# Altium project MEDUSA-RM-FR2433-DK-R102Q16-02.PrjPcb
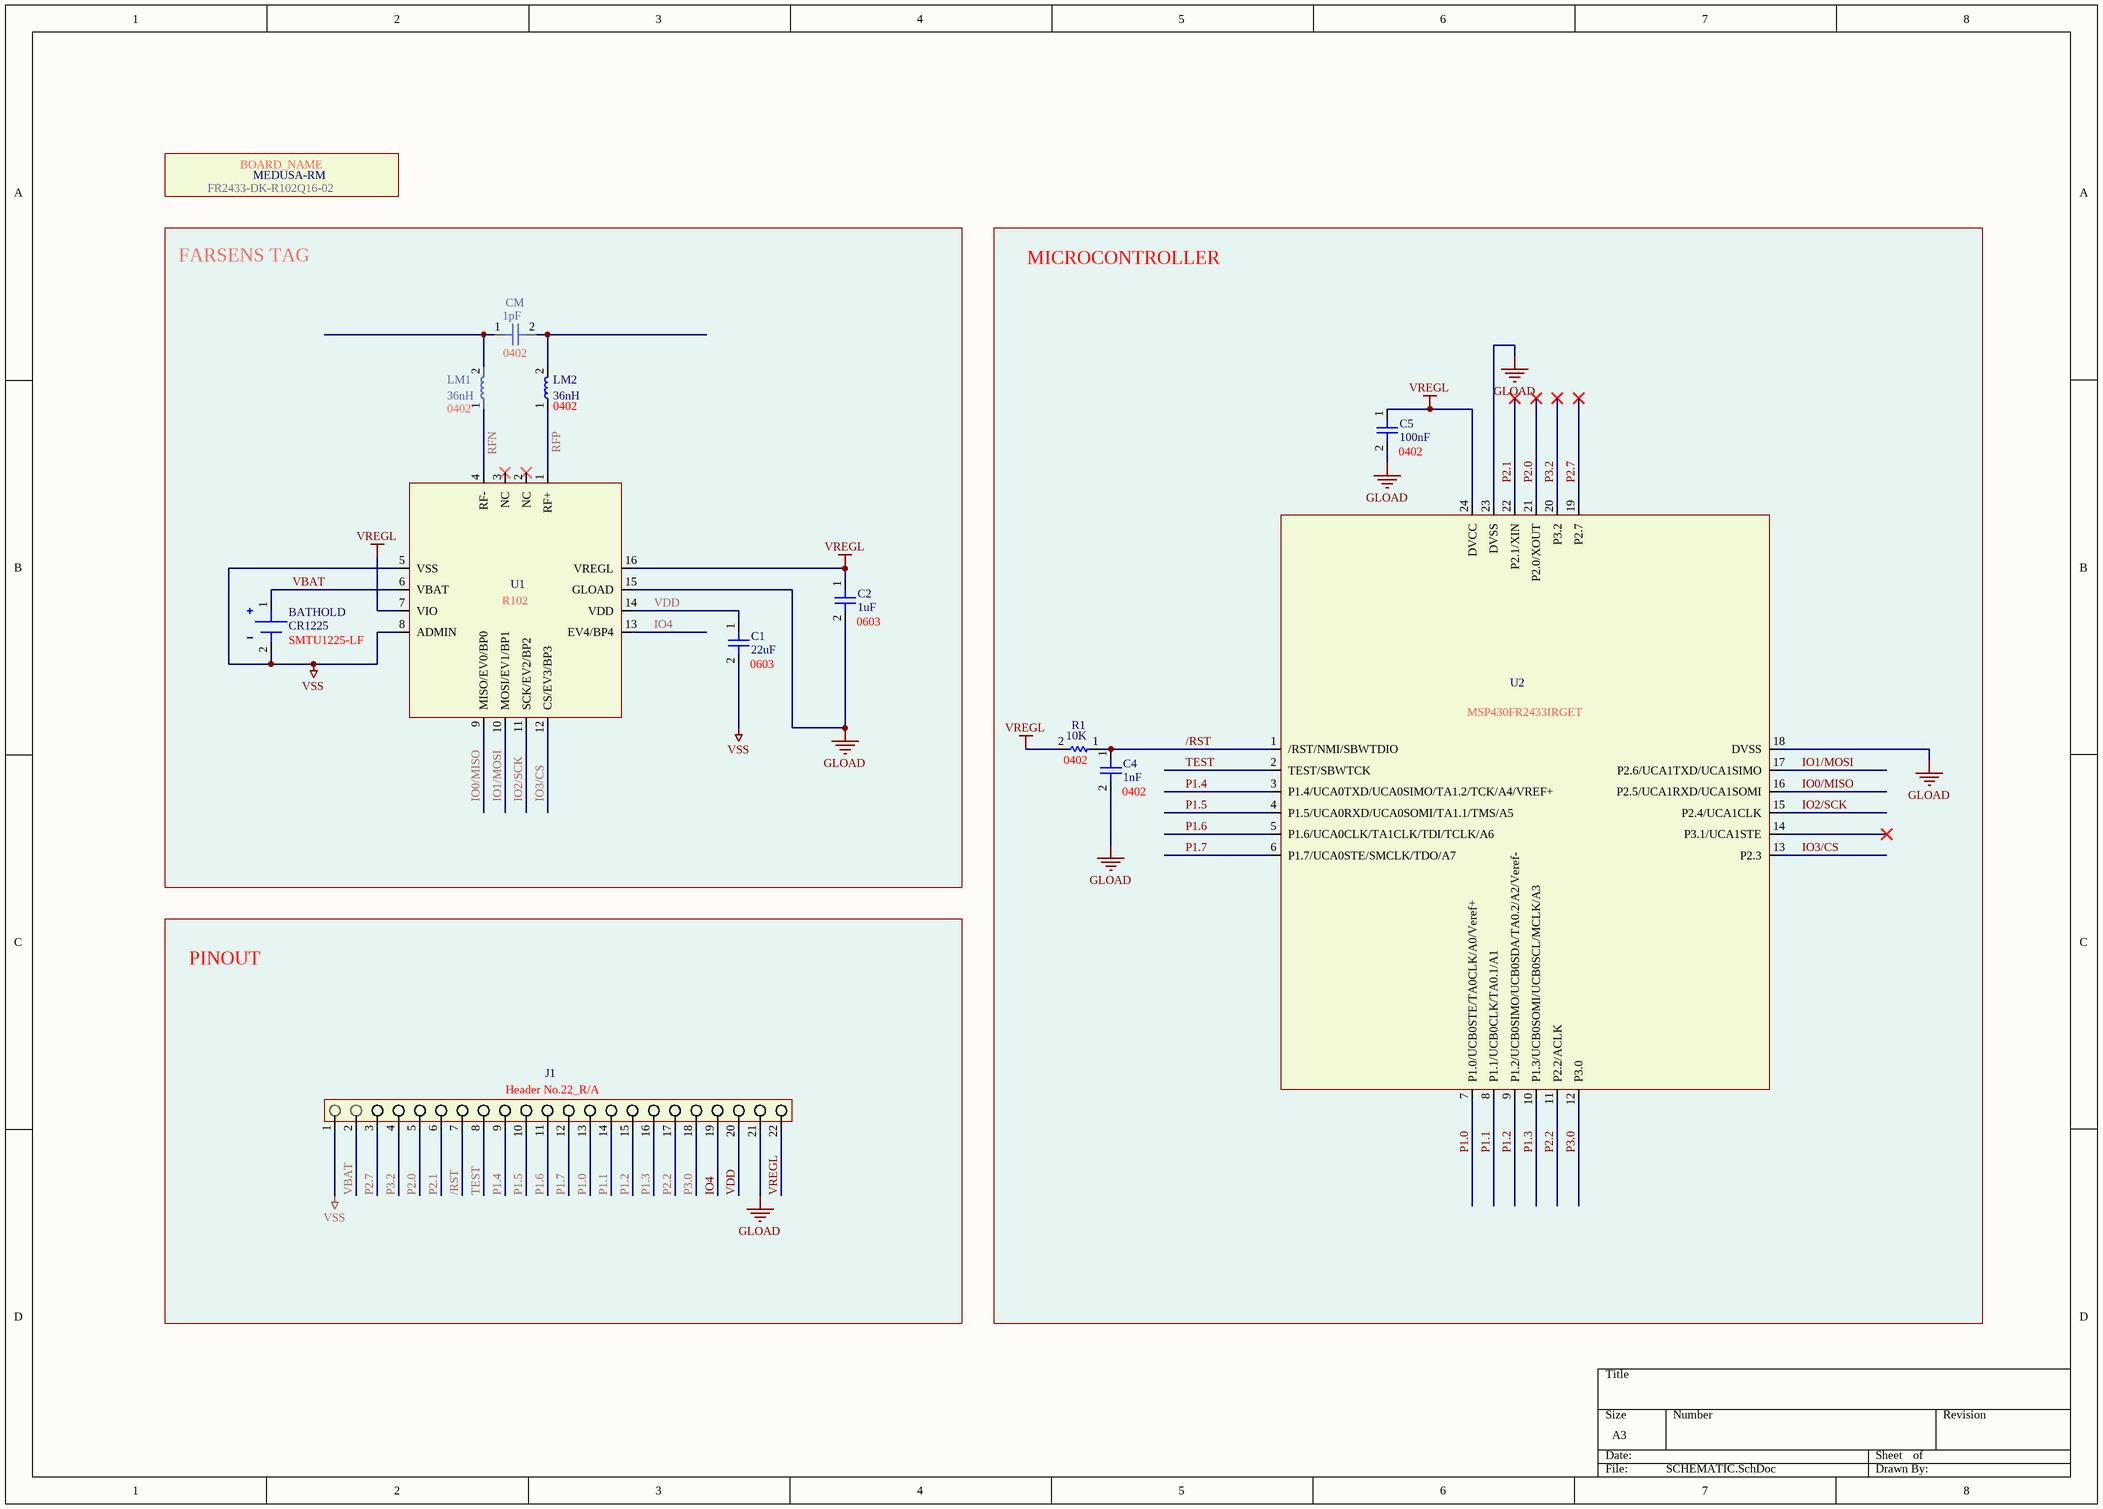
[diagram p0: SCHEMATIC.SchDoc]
1 sheet, 13 parts. Net scope: global (net labels, ports and power ports of the same name join across sheets).
Board file: LAYOUT.PcbDoc

## Sheet SCHEMATIC.SchDoc
size A3

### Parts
BATHOLD  03 Value: CR1225  [SMTU1225-LF]  (hidden comment: SMTU1225-LF)
C1  03 Value: 22uF  05 Footprint: 0603  [LCR 0603 (1608)]  (hidden comment: Capacitor)
C2  03 Value: 1uF  05 Footprint: 0603  [LCR 0603 (1608)]  (hidden comment: Capacitor)
C4  03 Value: 1nF  05 Footprint: 0402  [LCR 0402 (1005)]  (hidden comment: Capacitor)
C5  03 Value: 100nF  05 Footprint: 0402  [LCR 0402 (1005)]  (hidden comment: Capacitor)
CM  03 Value: 1pF  05 Footprint: 0402  [LCR 0402 (1005)]  (hidden comment: Capacitor)
J1  Header No.22_R/A  [61302211021]
LM1  03 Value: 36nH  05 Footprint: 0402  [LCR 0402 (1005)]  (hidden comment: Inductor)
LM2  03 Value: 36nH  05 Footprint: 0402  [LCR 0402 (1005)]  (hidden comment: Inductor)
MEDUSA-RM  02 Description: FR2433-DK-R102Q16-02  [BOARD_NAME]  (hidden comment: BOARD_NAME)
R1  03 Value: 10K  05 Footprint: 0402  [LCR 0402 (1005)]  (hidden comment: Resistor)
U1  R102  [R102]
U2  MSP430FR2433IRGET  [MSP430FR2433IRGET]

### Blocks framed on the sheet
FARSENS TAG: BATHOLD C1 C2 CM LM1 LM2 U1
MICROCONTROLLER: C4 C5 R1 U2

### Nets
GLOAD: C2.2 C4.2 C5.2 J1.21 U1.15(GLOAD) U2.18(DVSS) U2.23(DVSS)
VREGL: C2.1 C5.1 J1.22 R1.2 U1.7(VIO) U1.16(VREGL) U2.24(DVCC)
VSS: BATHOLD.2 C1.2 J1.1 U1.5(VSS) U1.8(ADMIN)
/RST: C4.1 J1.7 R1.1 U2.1(/RST/NMI/SBWTDIO)
IO0/MISO: U1.9(MISO/EV0/BP0) U2.16(P2.5/UCA1RXD/UCA1SOMI)
IO1/MOSI: U1.10(MOSI/EV1/BP1) U2.17(P2.6/UCA1TXD/UCA1SIMO)
IO2/SCK: U1.11(SCK/EV2/BP2) U2.15(P2.4/UCA1CLK)
IO3/CS: U1.12(CS/EV3/BP3) U2.13(P2.3)
IO4: J1.19 U1.13(EV4/BP4)
P1.0: J1.13 U2.7(P1.0/UCB0STE/TA0CLK/A0/Veref+)
P1.1: J1.14 U2.8(P1.1/UCB0CLK/TA0.1/A1)
P1.2: J1.15 U2.9(P1.2/UCB0SIMO/UCB0SDA/TA0.2/A2/Veref-)
P1.3: J1.16 U2.10(P1.3/UCB0SOMI/UCB0SCL/MCLK/A3)
P1.4: J1.9 U2.3(P1.4/UCA0TXD/UCA0SIMO/TA1.2/TCK/A4/VREF+)
P1.5: J1.10 U2.4(P1.5/UCA0RXD/UCA0SOMI/TA1.1/TMS/A5)
P1.6: J1.11 U2.5(P1.6/UCA0CLK/TA1CLK/TDI/TCLK/A6)
P1.7: J1.12 U2.6(P1.7/UCA0STE/SMCLK/TDO/A7)
P2.0: J1.5 U2.21(P2.0/XOUT)
P2.1: J1.6 U2.22(P2.1/XIN)
P2.2: J1.17 U2.11(P2.2/ACLK)
P2.7: J1.3 U2.19(P2.7)
P3.0: J1.18 U2.12(P3.0)
P3.2: J1.4 U2.20(P3.2)
RFN: LM1.1 U1.4(RF-)
RFP: LM2.1 U1.1(RF+)
TEST: J1.8 U2.2(TEST/SBWTCK)
VBAT: BATHOLD.1 J1.2 U1.6(VBAT)
VDD: C1.1 J1.20 U1.14(VDD)
NetCM_1: CM.1 LM1.2
NetCM_2: CM.2 LM2.2

Not connected (* = marked no-connect by the designer): U1 2(NC)* 3(NC)*; U2 14(P3.1/UCA1STE)*

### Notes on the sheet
- PINOUT

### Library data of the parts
BATHOLD = SMTU1225-LF: Battery holder; 06 Manufacturer: RENATA
C1 = Capacitor: 06 Manufacturer: AVX; 07 Manufacturer Reference: 06036D226MAT2A; 02 Description: Ceramic Capacitor
C2 = Capacitor: 06 Manufacturer: MURATA; 07 Manufacturer Reference: GRM188R71C105KA12D; 02 Description: Ceramic Capacitor
C4 = Capacitor: 06 Manufacturer: MURATA; 07 Manufacturer Reference: GRM155R71H102KA01D; 02 Description: Ceramic Capacitor
C5 = Capacitor: 06 Manufacturer: MURATA; 07 Manufacturer Reference: GRM155R71C104KA88D; 02 Description: Ceramic Capacitor
CM = Capacitor: 06 Manufacturer: Johanson Dielectrics; 07 Manufacturer Reference: 500R07S1R0BV4T; 02 Description: Ceramic Capacitor
J1 = Header No.22_R/A: 1-Row, 22-Pin, Pitch 2.54mm, Right Angle; 06 Manufacturer: WURTH; 02 Description: Male, Thru Hole, R/A
LM1 LM2 = Inductor: 06 Manufacturer: MURATA; 07 Manufacturer Reference: LQW15AN36NG00D
MEDUSA-RM = BOARD_NAME: LOGO FARSENS
R1 = Resistor: 06 Manufacturer: PANASONIC; 07 Manufacturer Reference: ERJ-2RKF1002X
U1 = R102: RFID TAG; 06 Manufacturer: FARSENS; 07 Manufacturer Reference: R102Q16; 01 Type: IC; 02 Description: RFID TAG IC; 11 RS Reference: NA
U2 = MSP430FR2433IRGET: Mixed-Signal Microcontroller; 06 Manufacturer: TEXAS INSTRUMENTS; 01 Type: IC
